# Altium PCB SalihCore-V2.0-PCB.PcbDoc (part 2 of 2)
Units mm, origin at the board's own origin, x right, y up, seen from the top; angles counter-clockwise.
Board outline 97.26 x 87.25 mm, 4 copper layers (L1(sig), L2(GND), L3(PWR), L4(sig)), stack 1.589 mm thick; 79 components, 110 nets, 368 pads, 235 vias.
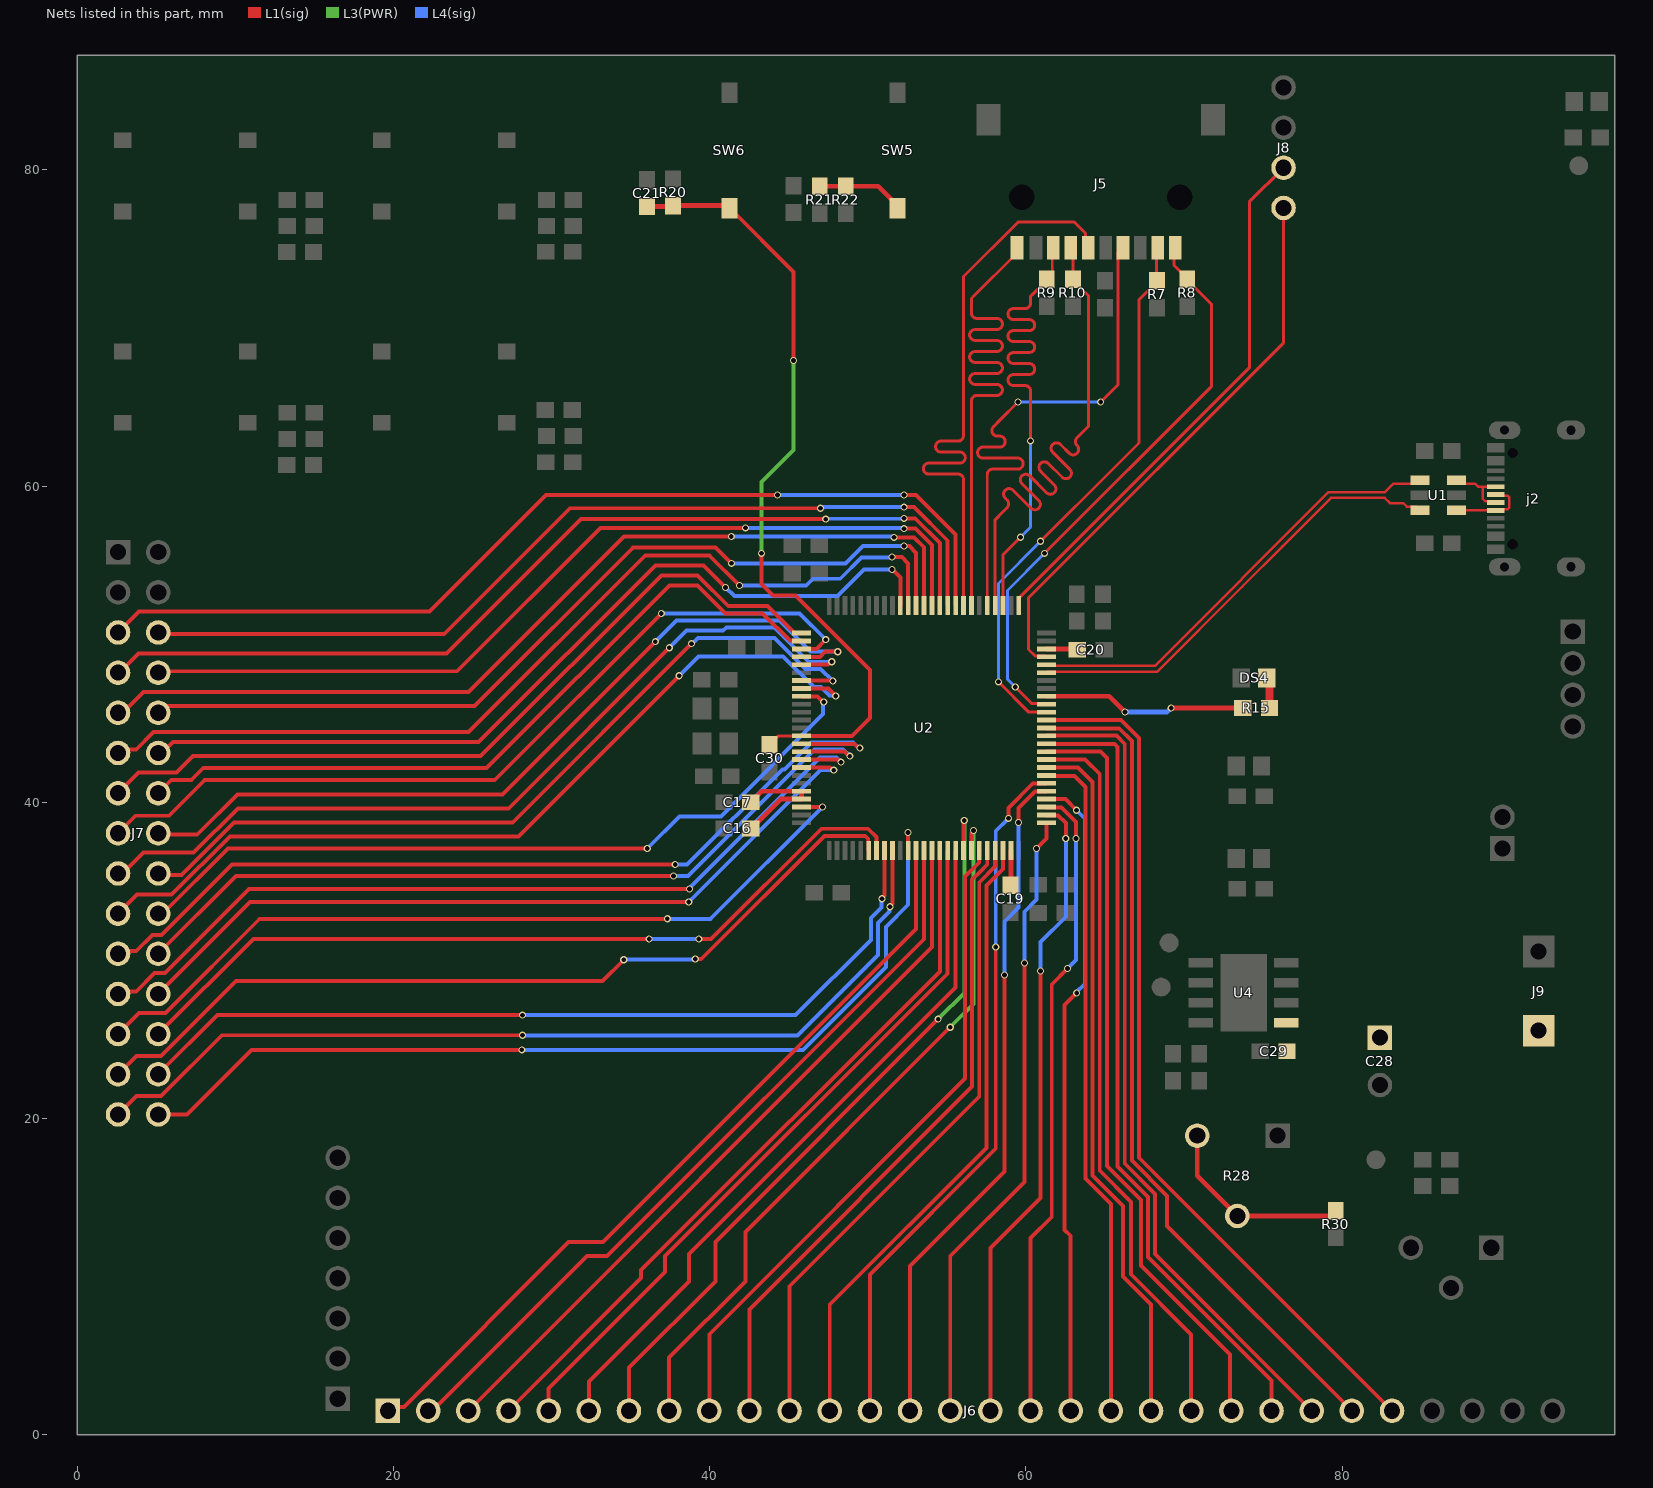
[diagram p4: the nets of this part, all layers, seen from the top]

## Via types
v1: diameter 0.45, hole 0.3, L1(sig) to L4(sig), tented both sides, 211 vias
v2: diameter 0.5, hole 0.3, L1(sig) to L4(sig), tented both sides, 24 vias

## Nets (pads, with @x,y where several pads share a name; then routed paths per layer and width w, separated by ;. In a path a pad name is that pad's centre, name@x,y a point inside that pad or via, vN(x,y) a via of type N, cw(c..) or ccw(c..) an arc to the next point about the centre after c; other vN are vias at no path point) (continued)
NetR28_1: R28.1 R28.3 R30.2 | length 12.5
  L1(sig) w0.3: R28.3@70.843,18.923 70.843,16.383 R28.1@73.383,13.843 79.264,13.843 R30.2@79.606,14.185
nRST: C21.2 C30.2 R20.2 SW6.2 U2.14 | length 50.9
  L1(sig) w0.2: C30.2@43.792,43.649 43.792,43.699 44.192,44.099 44.242,44.099 44.35,44.207 U2.14@45.813,44.207
  L1(sig) w0.25: SW6.2@41.252,77.757 41.252,77.607 45.316,73.543 v1(45.316,67.945) ; v1(43.284,55.753) 43.284,53.82 44.018,53.086 45.443,53.086 50.142,48.387 50.142,45.339 49.01,44.207 U2.14@45.813,44.207
  L1(sig) w0.3: C21.2@36.037,77.686 37.649,77.686 R20.2@37.688,77.725 37.721,77.757 SW6.2@41.252,77.757
  L3(PWR) w0.25: v1(43.284,55.753) 43.284,60.268 45.316,62.3 v1(45.316,67.945)
PA0: J7.25 U2.23 | length 51.8
  L1(sig) w0.25: J7.25@2.59,25.346 3.914,26.67 5.581,26.67 11.55,32.639 v1(37.331,32.639) ; U2.23@45.813,39.707 v1(47.138,39.707)
  L4(sig) w0.25: v1(37.331,32.639) 40.07,32.639 v1(47.138,39.707)
PA6: J7.27 U2.31 | length 54.5
  L1(sig) w0.25: J7.27@2.59,22.806 3.757,23.972 5.312,23.972 10.042,28.702 33.23,28.702 v1(34.573,30.046) ; v1(39.093,30.099) 39.474,30.099 47.257,37.882 49.848,37.882 50.038,37.692 50.038,36.982 U2.31@50.063,36.957
  L4(sig) w0.25: v1(34.573,30.046) 34.6,30.072 39.067,30.072 v1(39.093,30.099)
PA7: J7.26 U2.32 | length 51.9
  L1(sig) w0.25: J7.26@5.13,25.346 11.146,31.361 v1(36.18,31.361) ; v1(39.324,31.361) 40.1,31.361 47.071,38.332 50.034,38.332 50.563,37.803 U2.32@50.563,36.957
  L4(sig) w0.25: v1(36.18,31.361) v1(39.324,31.361)
PB1: J7.30 U2.36 | length 60.1
  L1(sig) w0.25: J7.30@5.13,20.266 6.94,20.266 11.026,24.352 v1(28.127,24.352) ; v1(52.555,38.1) 52.559,38.096 52.559,36.961 U2.36@52.563,36.957
  L4(sig) w0.25: v1(28.127,24.352) 45.919,24.352 51.158,29.591 51.158,32.131 52.555,33.528 v1(52.555,38.1)
PB2: J6.1 U2.37 | length 51
  L1(sig) w0.25: J6.1@19.662,1.524 19.904,1.766 20.666,1.766 31.092,12.192 33.251,12.192 53.063,32.004 U2.37@53.063,36.957
PB3: J7.10 U2.89 | length 56.6
  L1(sig) w0.25: J7.10@5.184,45.72 5.565,46.101 25.139,46.101 35.172,56.134 40.379,56.134 v1(41.395,55.118) ; v1(52.301,56.214) 52.312,56.203 52.639,56.203 53.063,55.779 U2.89@53.063,52.457
  L4(sig) w0.25: v1(41.395,55.118) 48.603,55.118 49.698,56.214 v1(52.301,56.214)
PB4: J7.11 U2.90 | length 59.5
  L1(sig) w0.25: J7.11@2.59,43.126 2.815,43.351 3.74,43.351 4.839,44.45 24.758,44.45 35.934,55.626 39.982,55.626 v1(41.887,53.721) ; v1(51.539,55.514) 52.159,55.514 52.563,55.11 U2.90@52.563,52.457
  L4(sig) w0.25: v1(41.887,53.721) 46.115,53.721 46.538,54.144 48.265,54.144 49.62,55.499 51.524,55.499 v1(51.539,55.514)
PB5: J7.12 U2.91 | length 55.3
  L1(sig) w0.25: J7.12@5.13,43.126 5.378,43.126 6.067,43.815 7.851,43.815 25.393,43.815 36.569,54.991 39.617,54.991 v1(41.014,53.594) ; v1(51.539,54.737) 51.562,54.737 52.063,54.236 U2.91@52.063,52.457
  L4(sig) w0.25: v1(41.014,53.594) 41.564,53.044 48.084,53.044 49.777,54.737 v1(51.539,54.737)
PB10: J6.11 U2.47 | length 40.8
  L1(sig) w0.25: J6.11@45.062,1.524 45.062,9.398 57.058,21.394 57.058,34.931 58.063,35.936 U2.47@58.063,36.957
PB11: J6.12 U2.48 | length 40
  L1(sig) w0.25: J6.12@47.602,1.524 47.602,8.234 57.508,18.14 57.508,34.745 58.563,35.8 U2.48@58.563,36.957
PB12: J6.15 U2.51 | length 39.7
  L1(sig) w0.25: J6.15@55.222,1.524 55.222,11.299 59.921,15.998 v1(59.921,29.845) ; v1(60.683,37.084) 61.313,37.714 U2.51@61.313,38.707
  L4(sig) w0.25: v1(59.921,29.845) 59.921,33.084 60.683,33.846 v1(60.683,37.084)
PB13: J6.16 U2.52 | length 40.6
  L1(sig) w0.25: J6.16@57.762,1.524 57.762,11.818 60.937,14.993 v1(60.937,29.337) ; U2.52@61.313,39.207 61.338,39.182 62.048,39.182 62.531,38.699 v1(62.531,37.719)
  L4(sig) w0.25: v1(60.937,29.337) 60.937,31.174 62.531,32.768 v1(62.531,37.719)
PB14: J6.17 U2.53 | length 40.7
  L1(sig) w0.25: J6.17@60.302,1.524 60.302,12.446 61.641,13.785 61.641,28.491 v1(62.639,29.489) ; U2.53@61.313,39.707 61.338,39.682 62.253,39.682 63.181,38.754 v1(63.181,37.719)
  L4(sig) w0.25: v1(62.639,29.489) 63.181,30.031 v1(63.181,37.719)
PB15: J6.18 U2.54 | length 41.1
  L1(sig) w0.25: U2.54@61.313,40.207 62.506,40.207 v1(63.21,39.503) ; J6.18@62.842,1.524 62.842,12.573 62.461,12.954 62.461,27.185 v1(63.216,27.94)
  L4(sig) w0.25: v1(63.21,39.503) 63.731,38.982 63.731,28.509 63.216,27.994 v1(63.216,27.94)
PC0: J7.21 U2.15 | length 56.4
  L1(sig) w0.25: J7.21@2.59,30.426 2.756,30.591 3.74,30.591 4.772,31.623 5.343,31.623 9.788,36.068 v1(37.823,36.068) ; U2.15@45.813,43.707 49.18,43.707 49.453,43.434 v1(49.507,43.434)
  L4(sig) w0.25: v1(37.823,36.068) 38.586,36.068 44.601,42.084 44.743,42.084 46.458,43.799 49.088,43.799 49.453,43.434 v1(49.507,43.434)
PC1: J7.22 U2.16 | length 52.4
  L1(sig) w0.25: J7.22@5.13,30.426 10.052,35.348 10.391,35.348 v1(37.712,35.348) ; U2.16@45.813,43.207 48.537,43.207 48.818,42.926 v1(48.872,42.926)
  L4(sig) w0.25: v1(37.712,35.348) 38.643,35.348 46.644,43.349 48.447,43.349 48.87,42.926 v1(48.872,42.926)
PC2: J7.23 U2.17 | length 54.6
  L1(sig) w0.25: J7.23@2.59,27.886 2.756,28.051 3.74,28.051 4.899,29.21 5.565,29.21 10.878,34.523 v1(38.733,34.523) ; U2.17@45.813,42.707 48.094,42.707 48.256,42.545 v1(48.31,42.545)
  L4(sig) w0.25: v1(38.733,34.523) 38.733,34.572 46.994,42.832 48.023,42.832 v1(48.31,42.545)
PC3: J7.24 U2.18 | length 50.7
  L1(sig) w0.25: J7.24@5.13,27.886 10.942,33.698 v1(38.686,33.698) ; U2.18@45.813,42.207 47.632,42.207 47.802,42.037 v1(47.856,42.037)
  L4(sig) w0.25: v1(38.686,33.698) 47.025,42.037 v1(47.856,42.037)
PC4: J7.28 U2.33 | length 54.6
  L1(sig) w0.25: J7.28@5.13,22.806 8.867,26.543 10.772,26.543 v1(28.171,26.543) ; v1(50.904,33.909) 50.904,33.963 51.063,34.122 U2.33@51.063,36.957
  L4(sig) w0.25: v1(28.171,26.543) 45.443,26.543 50.2,31.3 50.2,32.697 50.862,33.359 50.862,33.629 50.866,33.633 50.866,33.871 v1(50.904,33.909)
PC5: J7.29 U2.34 | length 59.2
  L1(sig) w0.25: J7.29@2.59,20.266 3.757,21.432 5.312,21.432 9.153,25.273 v1(28.171,25.273) ; v1(51.412,33.401) 51.412,33.455 51.563,33.606 U2.34@51.563,36.957
  L4(sig) w0.25: v1(28.171,25.273) 28.186,25.258 45.556,25.258 50.65,30.353 50.65,32.385 51.374,33.109 51.374,33.363 v1(51.412,33.401)
PC6: J6.25 U2.63 | length 53.9
  L1(sig) w0.25: U2.63@61.313,44.707 61.338,44.682 65.911,44.682 66.71,43.883 66.71,17.34 68.938,15.112 68.938,13.208 J6.25@80.622,1.524
PC7: J6.26 U2.64 | length 55.3
  L1(sig) w0.25: U2.64@61.47,45.207 66.022,45.207 67.16,44.069 67.16,17.526 J6.26@83.162,1.524
PC13: J7.18 U2.7 | length 52.1
  L1(sig) w0.25: J7.18@5.13,35.506 5.218,35.418 6.598,35.418 9.915,38.735 27.552,38.735 v1(38.855,50.038) ; U2.7@45.813,47.707 47.684,47.707 47.756,47.635 v1(47.798,47.677)
  L4(sig) w0.25: v1(38.855,50.038) 38.909,50.038 39.279,50.408 44.114,50.408 46.077,48.445 47.03,48.445 v1(47.798,47.677)
PC14: J7.19 U2.8 | length 55.5
  L1(sig) w0.25: J7.19@2.59,32.966 3.787,34.163 5.98,34.163 9.663,37.846 27.917,37.846 v1(38.077,48.006) ; U2.8@45.813,47.207 47.512,47.207 v1(47.983,46.736)
  L4(sig) w0.25: v1(38.077,48.006) 39.305,49.234 44.652,49.234 46.594,47.292 47.062,47.292 47.58,46.774 47.945,46.774 v1(47.983,46.736)
PC15: J7.20 U2.9 | length 49.6
  L1(sig) w0.25: J7.20@5.13,32.966 5.419,32.966 9.537,37.084 v1(36.061,37.084) ; U2.9@45.813,46.707 46.815,46.707 47.167,46.355 v1(47.221,46.355)
  L4(sig) w0.25: v1(36.061,37.084) 38.093,39.116 40.722,39.116 47.183,45.577 47.183,46.317 v1(47.221,46.355)
PD3: J7.5 U2.84 | length 62.1
  L1(sig) w0.25: J7.5@2.59,50.746 3.914,52.07 22.284,52.07 29.65,59.436 v1(44.3,59.436) ; v1(52.301,59.436) 53.063,59.436 55.563,56.936 U2.84@55.563,52.457
  L4(sig) w0.25: v1(44.3,59.436) v1(52.301,59.436)
PD4: J7.6 U2.85 | length 58.2
  L1(sig) w0.25: J7.6@5.13,50.658 23.22,50.658 31.164,58.603 v1(47.023,58.603) ; v1(52.301,58.674) 52.936,58.674 55.063,56.547 U2.85@55.063,52.457
  L4(sig) w0.25: v1(47.023,58.603) 47.061,58.641 47.203,58.641 47.236,58.674 v1(52.301,58.674)
PD5: J7.7 U2.86 | length 60.6
  L1(sig) w0.25: J7.7@2.59,48.118 3.875,49.403 23.361,49.403 31.87,57.912 v1(47.348,57.912) ; v1(52.301,57.964) 53.01,57.964 54.563,56.411 U2.86@54.563,52.457
  L4(sig) w0.25: v1(47.348,57.912) 47.374,57.938 52.276,57.938 v1(52.301,57.964)
PD6: J7.8 U2.87 | length 57
  L1(sig) w0.25: J7.8@5.13,48.293 24.029,48.293 33.098,57.362 v1(42.268,57.362) ; v1(52.301,57.314) 52.304,57.311 53.026,57.311 54.063,56.274 U2.87@54.063,52.457
  L4(sig) w0.25: v1(42.268,57.362) 52.112,57.362 52.122,57.352 52.263,57.352 v1(52.301,57.314)
PD7: J7.9 U2.88 | length 59.6
  L1(sig) w0.25: J7.9@2.59,45.666 2.87,45.666 4.194,46.99 24.758,46.99 34.58,56.812 v1(41.379,56.812) ; v1(51.666,56.764) 52.937,56.764 53.563,56.138 U2.88@53.563,52.457
  L4(sig) w0.25: v1(41.379,56.812) 41.471,56.812 41.472,56.811 51.565,56.811 51.612,56.764 v1(51.666,56.764)
PD8: J6.14 U2.55 | length 43.2
  L1(sig) w0.25: J6.14@52.682,1.524 52.682,10.674 58.651,16.643 v1(58.651,29.083) ; v1(59.54,38.735) 59.54,39.644 60.579,40.682 61.288,40.682 U2.55@61.313,40.707
  L4(sig) w0.25: v1(58.651,29.083) 58.651,32.45 59.54,33.339 v1(59.54,38.735)
PD9: J6.13 U2.56 | length 44.8
  L1(sig) w0.25: J6.13@50.142,1.524 50.142,10.138 58.101,18.097 v1(58.101,30.861) ; v1(58.905,38.989) 58.905,39.645 60.442,41.182 61.288,41.182 U2.56@61.313,41.207
  L4(sig) w0.25: v1(58.101,30.861) 58.101,38.185 v1(58.905,38.989)
PD10: J6.19 U2.57 | length 42.9
  L1(sig) w0.25: U2.57@61.313,41.707 61.338,41.682 63.07,41.682 63.766,40.986 63.766,16.22 65.382,14.604 J6.19@65.382,1.524
PD11: J6.20 U2.58 | length 44.6
  L1(sig) w0.25: U2.58@61.313,42.207 63.307,42.207 64.216,41.298 64.216,16.406 66.144,14.478 66.144,10.028 67.922,8.25 J6.20@67.922,1.524
PD12: J6.21 U2.59 | length 46.4
  L1(sig) w0.25: U2.59@61.313,42.707 63.754,42.707 64.678,41.783 64.678,16.706 66.652,14.732 66.652,10.157 70.462,6.347 J6.21@70.462,1.524
PD13: J6.22 U2.60 | length 48.5
  L1(sig) w0.25: U2.60@61.313,43.207 64.72,43.207 65.128,42.799 65.128,17.012 67.276,14.864 67.276,10.714 72.91,5.08 72.91,1.616 J6.22@73.002,1.524
PD14: J6.23 U2.61 | length 50.6
  L1(sig) w0.25: U2.61@61.313,43.707 65.613,43.707 65.81,43.51 65.81,16.967 67.726,15.051 67.726,11.244 75.542,3.428 J6.23@75.542,1.524
PD15: J6.24 U2.62 | length 52.2
  L1(sig) w0.25: U2.62@61.313,44.207 61.338,44.232 65.725,44.232 66.26,43.696 66.26,17.153 68.176,15.237 68.176,11.43 J6.24@78.082,1.524
PE2: J7.13 U2.1 | length 50.4
  L1(sig) w0.25: J7.13@2.59,40.586 3.885,41.88 6.298,41.88 7.343,42.926 25.52,42.926 36.95,54.356 39.236,54.356 41.183,52.409 43.661,52.409 45.363,50.707 U2.1@45.813,50.707
PE3: J7.14 U2.2 | length 47.6
  L1(sig) w0.25: J7.14@5.13,40.586 5.975,41.43 7.245,41.43 7.978,42.164 25.901,42.164 37.458,53.721 39.235,53.721 40.997,51.959 43.352,51.959 45.079,50.232 45.788,50.232 U2.2@45.813,50.207
PE4: J7.15 U2.3 | length 53
  L1(sig) w0.25: J7.15@2.59,38.046 3.7,39.155 5.808,39.155 8.055,41.402 26.409,41.402 v1(36.95,51.943) ; U2.3@45.813,49.707 46.763,49.707 v1(47.348,50.292)
  L4(sig) w0.25: v1(36.95,51.943) 36.966,51.959 45.681,51.959 v1(47.348,50.292)
PE5: J7.16 U2.4 | length 51.9
  L1(sig) w0.25: J7.16@5.13,38.046 5.218,37.958 7.599,37.958 10.153,40.513 26.917,40.513 v1(36.569,50.165) ; U2.4@45.813,49.207 46.994,49.207 47.317,49.53 v1(48.11,49.53)
  L4(sig) w0.25: v1(36.569,50.165) 37.913,51.509 44.411,51.509 46.39,49.53 v1(48.11,49.53)
PE6: J7.17 U2.5 | length 54.5
  L1(sig) w0.25: J7.17@2.59,35.506 2.87,35.506 4.194,36.83 7.374,36.83 10.168,39.624 27.298,39.624 v1(37.458,49.784) ; U2.5@45.813,48.707 47.487,48.707 47.675,48.895 v1(47.729,48.895)
  L4(sig) w0.25: v1(37.458,49.784) 38.532,50.858 40.857,50.858 41.058,51.059 44.099,51.059 46.263,48.895 v1(47.729,48.895)
PE7: J6.2 U2.38 | length 49.3
  L1(sig) w0.25: J6.2@22.202,1.524 22.449,1.524 22.741,1.815 22.764,1.815 32.251,11.303 33.521,11.303 53.563,31.345 U2.38@53.563,36.957
PE8: J6.3 U2.39 | length 47.6
  L1(sig) w0.25: J6.3@24.742,1.524 54.063,30.845 U2.39@54.063,36.957
PE9: J6.4 U2.40 | length 46.7
  L1(sig) w0.25: J6.4@27.282,1.524 35.664,9.906 35.664,10.414 54.563,29.313 U2.40@54.563,36.957
PE10: J6.5 U2.41 | length 45.9
  L1(sig) w0.25: J6.5@29.822,1.524 29.822,2.921 37.188,10.287 37.188,11.302 55.063,29.177 U2.41@55.063,36.957
PE11: J6.6 U2.42 | length 45
  L1(sig) w0.25: J6.6@32.362,1.524 32.362,3.362 38.712,9.712 38.712,11.43 55.563,28.281 U2.42@55.563,36.957
PE12: J6.7 U2.43 | length 48
  L1(sig) w0.25: J6.7@34.902,1.524 34.902,4.251 40.363,9.712 40.363,12.192 v1(54.46,26.289) ; U2.43@56.063,36.957 56.063,38.673 56.073,38.682 56.073,38.824 v1(56.111,38.862)
  L3(PWR) w0.25: v1(54.46,26.289) 56.111,27.94 v1(56.111,38.862)
PE13: J6.8 U2.44 | length 46
  L1(sig) w0.25: J6.8@37.442,1.524 37.442,4.886 42.268,9.712 42.268,12.827 v1(55.222,25.781) ; U2.44@56.563,36.957 56.563,38.046 56.69,38.173 v1(56.69,38.227)
  L3(PWR) w0.25: v1(55.222,25.781) 56.69,27.248 v1(56.69,38.227)
PE14: J6.9 U2.45 | length 42.5
  L1(sig) w0.25: J6.9@39.982,1.524 39.982,6.35 56.158,22.526 56.158,35.304 57.038,36.184 57.038,36.932 U2.45@57.063,36.957
PE15: J6.10 U2.46 | length 41.7
  L1(sig) w0.25: J6.10@42.522,1.524 42.522,7.933 56.608,22.019 56.608,35.117 57.127,35.636 57.563,36.072 U2.46@57.563,36.957
RED: DS4.A R15.2 | length 2
  L1(sig) w0.5: DS4.A@75.237,47.879 75.414,47.702 R15.2@75.414,45.974
RED_LED: R15.1 U2.67 | length 12.9
  L1(sig) w0.3: U2.67@61.313,46.707 65.284,46.707 v1(66.271,45.72) ; v1(69.192,45.974) R15.1@73.714,45.974
  L4(sig) w0.3: v1(66.271,45.72) 68.938,45.72 v1(69.192,45.974)
SDIO_CD: J5.9 U2.82 | length 37.7
  L1(sig) w0.187: U2.82@56.563,52.457 56.563,64.6 56.563,65.389 cw(c56.911,65.389) 56.911,65.737 58.174,65.737 ccw(c58.174,66.085) 58.521,66.085 ccw(c58.174,66.085) 58.174,66.432 56.798,66.432 cw(c56.798,66.78) 56.451,66.78 cw(c56.798,66.78) 56.798,67.128 58.176,67.128 ccw(c58.176,67.475) 58.523,67.475 ccw(c58.176,67.475) 58.176,67.823 56.798,67.823 cw(c56.798,68.171) 56.451,68.171 cw(c56.798,68.171) 56.798,68.518 58.177,68.518 ccw(c58.177,68.866) 58.525,68.866 ccw(c58.177,68.866) 58.177,69.214 56.798,69.214 cw(c56.798,69.561) 56.451,69.561 cw(c56.798,69.561) 56.798,69.909 58.179,69.909 ccw(c58.179,70.257) 58.527,70.257 ccw(c58.179,70.257) 58.179,70.604 56.911,70.604 cw(c56.911,70.952) 56.563,70.952 56.563,71.872 56.7,72.009 59.373,74.682 J5.9@59.373,75.032
SDIO_CK: J5.5 U2.80 | length 35.6
  L1(sig) w0.187: U2.80@57.563,52.457 57.563,59.944 57.563,60.733 cw(c57.911,60.733) 57.911,61.081 59.486,61.081 ccw(c59.486,61.428) 59.834,61.428 ccw(c59.486,61.428) 59.486,61.776 57.298,61.776 cw(c57.298,62.124) 56.951,62.124 cw(c57.298,62.124) 57.298,62.471 58.351,62.471 ccw(c58.351,62.819) 58.699,62.819 ccw(c58.351,62.819) 58.351,63.167 58.196,63.167 cw(c58.196,63.514) 57.951,63.76 58.325,64.135 v1(59.506,65.315) ; v1(64.737,65.329) 65.841,66.433 65.841,74.8 J5.5@66.073,75.032
  L4(sig) w0.187: v1(59.506,65.315) 59.513,65.322 64.73,65.322 v1(64.737,65.329)
SDIO_CMD: J5.3 U2.83 | length 38.9
  L1(sig) w0.187: U2.83@56.063,52.457 56.063,60.325 56.063,60.419 ccw(c55.716,60.419) 55.716,60.766 53.871,60.766 cw(c53.871,61.114) 53.523,61.114 cw(c53.871,61.114) 53.871,61.462 55.828,61.462 ccw(c55.828,61.809) 56.176,61.809 ccw(c55.828,61.809) 55.828,62.157 54.64,62.157 cw(c54.64,62.505) 54.292,62.505 cw(c54.64,62.505) 54.64,62.852 55.716,62.852 ccw(c55.716,63.2) 56.063,63.2 56.063,64.389 56.063,73.252 59.519,76.708 63.06,76.708 63.776,75.992 63.776,75.242 J5.3@63.947,75.071
SDIO_D1: J5.8 R8.1 U2.66 | length 36.7
  L1(sig) w0.187: v1(59.336,47.293) 60.366,46.263 61.257,46.263 U2.66@61.313,46.207 ; v1(61.191,55.753) 71.732,66.294 71.732,71.516 70.216,73.032 R8.1@70.216,73.082 70.216,73.132 69.373,73.975 J5.8@69.373,75.032
  L4(sig) w0.187: v1(59.336,47.293) 58.846,47.783 58.846,53.407 v1(61.191,55.753)
SDIO_D2: J5.1 R9.1 U2.78 | length 34.5
  L1(sig) w0.187: U2.78@58.563,52.457 58.563,55.665 v1(59.667,56.769) ; v1(60.302,62.865) 60.302,65.924 60.302,66.018 ccw(c59.955,66.018) 59.955,66.365 59.223,66.365 cw(c59.223,66.713) 58.875,66.713 cw(c59.223,66.713) 59.223,67.061 60.217,67.061 ccw(c60.217,67.408) 60.565,67.408 ccw(c60.217,67.408) 60.217,67.756 59.223,67.756 cw(c59.223,68.104) 58.875,68.104 cw(c59.223,68.104) 59.223,68.451 60.217,68.451 ccw(c60.217,68.799) 60.565,68.799 ccw(c60.217,68.799) 60.217,69.147 59.223,69.147 cw(c59.223,69.494) 58.875,69.494 cw(c59.223,69.494) 59.223,69.842 60.217,69.842 ccw(c60.217,70.19) 60.565,70.19 ccw(c60.217,70.19) 60.217,70.537 59.223,70.537 cw(c59.223,70.885) 58.875,70.885 cw(c59.223,70.885) 59.223,71.233 59.955,71.233 ccw(c59.955,71.58) 60.302,71.58 60.302,72.004 60.371,72.072 61.326,73.028 R9.1@61.326,73.078 61.673,73.425 J5.1@61.673,75.032
  L4(sig) w0.187: v1(59.667,56.769) 60.302,57.404 v1(60.302,62.865)
SDIO_D3: J5.2 R10.1 U2.79 | length 38.6
  L1(sig) w0.187: U2.79@58.063,52.457 58.063,57.883 58.562,58.382 58.753,58.573 58.819,58.639 ccw(c58.573,58.885) 58.819,59.131 58.7,59.25 cw(c58.946,59.496) 58.7,59.741 cw(c58.946,59.496) 59.191,59.741 60.327,58.606 ccw(c60.573,58.851) 60.819,58.606 ccw(c60.573,58.851) 60.819,59.097 59.753,60.164 cw(c59.998,60.41) 59.753,60.655 cw(c59.998,60.41) 60.244,60.655 61.31,59.589 ccw(c61.556,59.835) 61.802,59.589 ccw(c61.556,59.835) 61.802,60.081 60.936,60.947 cw(c61.182,61.193) 60.936,61.439 cw(c61.182,61.193) 61.428,61.439 62.293,60.573 ccw(c62.539,60.819) 62.785,60.573 ccw(c62.539,60.819) 62.785,61.064 61.699,62.15 cw(c61.945,62.396) 61.699,62.642 cw(c61.945,62.396) 62.191,62.642 62.751,62.082 ccw(c62.997,62.328) 63.243,62.082 ccw(c62.997,62.328) 63.243,62.574 cw(c63.488,62.819) 63.243,63.065 63.962,63.785 63.962,64.901 63.962,72.044 62.977,73.028 R10.1@62.977,73.078 62.977,74.828 J5.2@62.773,75.032
SDIO_DO: J5.7 R7.1 U2.65 | length 35.4
  L1(sig) w0.187: v1(58.27,47.625) 60.188,45.707 U2.65@61.313,45.707 ; v1(60.937,56.515) 65.509,61.087 67.16,62.738 67.16,66.802 67.16,71.793 68.273,72.906 J5.7@68.273,75.032
  L4(sig) w0.187: v1(58.27,47.625) 58.27,53.848 v1(60.937,56.515)
SW1: R21.2 R22.2 SW5.1 | length 5.6
  L1(sig) w0.3: R21.2@46.967,78.966 R22.2@48.618,78.966 50.654,78.966 51.888,77.732 SW5.1@51.888,77.582
SYS_SWCL: J8.2 U2.76 | length 34.6
  L1(sig) w0.2: U2.76@59.563,52.457 59.563,52.907 74.145,67.489 74.145,77.978 J8.2@76.304,80.137
SYS_SWDIO: J8.1 U2.72 | length 35.9
  L1(sig) w0.2: U2.72@61.313,49.207 61.263,49.257 60.589,49.257 60.175,49.671 60.175,52.953 76.304,69.082 J8.1@76.304,77.597
USB_N: j2.5 j2.7 U1.1 | length 5
  L1(sig) w0.158: U1.1@87.233,58.486 87.251,58.468 j2.5@89.732,58.468 89.803,58.538 90.474,58.538 90.567,58.631 90.567,59.305 90.474,59.397 89.803,59.397 j2.7@89.732,59.468
USB_OTG_FS_N: U1.6 U2.70 | length 28.5
  L1(sig) w0.158: U2.70@61.313,48.207 61.383,48.276 68.32,48.276 73.681,53.638 76.233,56.189 79.303,59.259 82.704,59.259 83.035,58.928 83.875,58.928 84.096,58.707 84.712,58.707 U1.6@84.933,58.486
USB_OTG_FS_P: U1.4 U2.71 | length 28.5
  L1(sig) w0.158: U2.71@61.313,48.707 61.383,48.638 68.17,48.638 79.153,59.621 82.712,59.621 83.256,60.165 84.712,60.165 U1.4@84.933,60.386
USB_P: j2.6 j2.8 U1.3 | length 4.4
  L1(sig) w0.158: U1.3@87.233,60.386 87.454,60.165 88.409,60.165 88.606,59.968 j2.8@89.732,59.968 ; 89.028,59.968 88.903,59.843 88.903,59.202 89.067,59.039 89.661,59.039 j2.6@89.732,58.968
VCAP1: C19.2 U2.49 | length 2.2
  L1(sig) w0.3: C19.2@59.032,34.759 59.063,34.79 U2.49@59.063,36.957
VCAP2: C20.2 U2.73 | length 2
  L1(sig) w0.3: U2.73@61.313,49.707 63.212,49.707 C20.2@63.262,49.657
VDDA: C16.2 C17.2 U2.21 U2.22 | length 8
  L1(sig) w0.3: C16.2@42.61,38.354 42.66,38.354 44.513,40.207 U2.22@45.813,40.207 U2.21@45.813,40.707 43.312,40.707 43.01,40.405 43.01,40.355 42.66,40.005 C17.2@42.61,40.005
VM: C28.1 C29.2 J9.2 U4.5
pads on no net: j2. j2.3 j2.9 J5. J5.10 SW1.2 SW1.4 SW2.2 SW2.4 SW3.2 SW3.4 SW4.2 SW4.4
copper on no net: | length 28.9
  L1(sig) w0.3: v1(89.004,73.012) 89.004,74.194 ; 90.362,66.027 90.362,68.248 90.377,68.263 90.377,70.599 90.594,70.816 90.594,73.938 ; 91.544,73.938 91.544,71.957 91.906,71.595 91.956,71.595 92.306,71.245 92.306,71.195 ; v1(92.306,68.44) 92.306,69.647 ; 92.494,73.938 94.209,73.938 94.338,74.067 95.221,74.067 96.229,75.076 96.229,76.249 ; 92.494,75.866 92.494,75.854 92.624,75.724 v1(93.207,75.724)
  L1(sig) w0.5: v1(78.701,68.326) 80.122,68.326 ; 81.722,68.326 81.811,68.238 81.811,66.51 81.899,66.421 ; 82.019,84.906 v1(82.019,86.106) ; v1(85.321,72.885) 86.801,72.885 86.845,72.929 ; v1(85.956,70.599) 87.327,70.599 ; v1(96.243,71.361) 96.243,73.063

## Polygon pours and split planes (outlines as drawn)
GND on L1(sig) "GND_L01_P025" (solid, pour order 25): 93.472,74.501 90.17,74.501 90.17,75.253 92.075,75.253 92.075,76.708 93.472,76.708
+3V3 on L1(sig) "+3V3_L01_P019" (solid, pour order 19): 74.465,81.28 74.526,84.074 83.67,84.074 83.664,86.224 88.14,86.224 88.14,77.47 84.647,77.47 84.647,69.342 88.14,69.342 88.14,66.802 89.639,66.802 89.639,65.278 79.225,65.278 79.101,81.28
no net on L1(sig) "NONET_L01_P006" (solid, pour order 6): 94.973,75.248 93.703,75.248 93.703,77.579 91.544,77.579 91.544,79.566 93.576,79.566 94.973,78.169
no net on L1(sig) "NONET_L01_P005" (solid, pour order 5): 92.052,75.311 91.036,75.311 91.036,76.581 89.258,78.105 89.258,86.36 92.052,86.36
+5V on L1(sig) "+5V_L01_P004" (solid, pour order 4): 90.821,76.683 90.821,75.302 86.172,75.32 86.172,74.865 85.063,74.871 85.049,74.858 85.042,74.864 85.042,76.714
MOTOR_OUT1 on L1(sig) "MOTOR_OUT1_L01_P010" (solid, pour order 10): 75.605,26.957 75.61,26.961 75.61,27.716 77.515,27.716 89.566,38.1 93.009,38.1 93.009,36.479 93.009,36.098 77.355,26.827 75.61,26.827 75.61,26.954
MOTOR_OUT2 on L1(sig) "MOTOR_OUT2_L01_P009" (solid, pour order 9): 75.61,30.256 86.121,40.767 93.136,40.767 93.136,37.338 85.486,37.338 77.515,29.367 75.61,29.367
VM on L1(sig) "VM_L01_P008" (solid, pour order 8): 75.61,26.446 75.61,23.398 94.608,23.398 94.608,27.813 87.623,27.813 87.623,27.051 77.993,27.051 77.388,26.446
GND on L1(sig) "GND_L01_P023" (solid, pour order 23): 90.391,53.92 90.393,53.92 90.393,56.4 89.191,56.4 89.191,56.188 88.242,56.172 88.242,53.92
GND on L1(sig) "GND_L01_P022" (solid, pour order 22): 90.391,64.516 90.393,64.516 90.393,62.036 89.191,62.036 89.191,62.249 88.242,62.264 88.242,64.516
+5V on L1(sig) "+5V_L01_P012" (solid, pour order 12): 88.369,57.277 88.369,56.261 88.877,56.261 88.935,56.515 90.274,56.515 90.528,56.769 91.798,56.769 91.798,57.785 90.528,57.785 90.528,57.277
+5V on L1(sig) "+5V_L01_P011" (solid, pour order 11): 88.369,61.214 88.369,62.23 88.877,62.23 88.935,61.976 90.274,61.976 90.528,61.722 91.544,61.722 91.544,60.804 90.528,60.804 90.528,61.214
GND on L1(sig) "GND_L01_P020" (solid, pour order 20): 46.586,46.454 46.586,45.895 42.444,45.895 41.633,45.085 40.49,45.085 40.49,48.768 43.157,48.768 44.046,47.879 44.046,46.454
GND on L1(sig) "GND_L01_P021" (solid, pour order 21): 40.173,44.45 40.173,41.021 37.315,41.021 37.315,44.45
GND on L1(sig) "GND_L01_P007" (solid, pour order 7): 72.054,23.652 72.054,29.367 70.149,29.367 70.149,30.383 72.054,30.383 72.054,31.653 75.483,31.653 75.483,29.005 77.388,29.005 77.388,28.224 75.356,28.224 75.356,23.652
+3V3 on L3(PWR) "+3V3_L03_P016" (solid, remove dead copper, pour order 16): 92.941,0 92.941,87.249 0,87.249 0,0
+5V on L3(PWR) "+5V_L03_P015" (solid, pour order 15): 97.259,0 83.256,0 83.256,3.81 86.264,3.81 86.268,4.496 86.591,58.547 83.256,58.547 83.256,62.23 89.893,62.23 89.893,71.841 84.686,71.841 84.686,77.737 92.56,77.737 92.665,87.249 97.259,87.249
GND on L2(GND) "GND_L02_P013" (solid, pour order 13): 0,0 0,87.249 97.259,87.249 97.259,0

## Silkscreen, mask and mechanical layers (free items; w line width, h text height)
Top Overlay:
  lines w0.3: 85.194,26.035 87.48,26.035 ; 86.337,24.638 86.337,27.178 ; 86.337,29.337 86.337,31.877
  text "BUTTON-1" at 30.959,79.234 h1.5 r90
  text "BUTTON-4" at 14.576,79.107 h1.5 r90
  text "RESET" at 38.642,73.473 h1.5
  text "BOOT-0" at 49.564,73.473 h1.5
  text "BUTTON-2" at 30.959,66.026 h1.5 r90
  text "BUTTON-3" at 14.576,65.772 h1.5 r90
  text "+3V3" at 83.217,65.513 h0.7
  text "+3V3  GND" at 7.485,55.255 h1.2
  text "+3V3  GND" at 7.485,52.697 h1.2
  text "PD3  PD4" at 7.485,50.139 h1.2
  text "PD5  PD6" at 7.485,47.581 h1.2
  text "RED" at 71.83,46.849 h0.7 r90
  text "PD7  PB3" at 7.485,45.023 h1.2
  text "I2C-LCD" at 91.002,44.542 h1.5 r90
  text "PB4  PB5" at 7.485,42.464 h1.2
  text "GREEN" at 71.957,40.993 h0.7 r90
  text "PE2  PE3" at 7.485,39.906 h1.2
  text "PE4  PE5" at 7.485,37.348 h1.2
  text "BLUE" at 71.898,35.407 h0.7 r90
  text "PE6  PC13" at 7.485,34.79 h1.2
  text "MOTOR-OUT" at 87.527,34.541 h1.5 r90
  text "PC14  PC15" at 7.485,32.232 h1.2
  text "IN2" at 68.378,31.994 h0.7
  text "PC0  PC1" at 7.485,29.674 h1.2
  text "PC2  PC3" at 7.485,27.116 h1.2
  text "IN1" at 67.87,26.66 h0.7
  text "PA0  PA7" at 7.485,24.557 h1.2
  text "FIXED" at 71.959,22.325 h0.7
  text "PA6  PC4" at 7.485,21.999 h1.2
  text "ADJ" at 68.203,21.817 h0.7 r90
  text "MOTOR-VM" at 88.239,20.273 h1.5
  text "PC5  PB1" at 7.485,19.441 h1.2
  text "MOTOR-CNT" at 80.136,18.269 h0.7
  text "GND" at 7.308,15.925 h1.2
  text "+3V3" at 7.308,13.363 h1.2
  text "LORA-AUX" at 7.308,10.802 h1.2
  text "ILIM Control" at 69.381,9.375 h1.5
  text "LORA-TXD" at 7.308,8.241 h1.2
  text "Motor Control" at 92.783,7.968 h1.5 r90
  text "LORA-RXD" at 7.308,5.68 h1.2
  text "LORA MODULE" at 5.348,4.311 h1.5 r90
  text "PB2" at 20.209,3.284 h1.2 r90
  text "PE7" at 22.745,3.284 h1.2 r90
  text "PE8" at 25.28,3.284 h1.2 r90
  text "PE9" at 27.816,3.284 h1.2 r90
  text "PE10" at 30.352,3.284 h1.2 r90
  text "PE11" at 32.887,3.284 h1.2 r90
  text "PE12" at 35.423,3.284 h1.2 r90
  text "PE13" at 37.958,3.284 h1.2 r90
  text "PE14" at 40.494,3.284 h1.2 r90
  text "PE15" at 43.03,3.284 h1.2 r90
  text "PE16" at 45.565,3.284 h1.2 r90
  text "PB11" at 48.101,3.284 h1.2 r90
  text "PD9" at 50.636,3.284 h1.2 r90
  text "PD8" at 53.172,3.284 h1.2 r90
  text "PB12" at 55.708,3.284 h1.2 r90
  text "PB13" at 58.243,3.284 h1.2 r90
  text "PB14" at 60.779,3.284 h1.2 r90
  text "PB15" at 63.315,3.284 h1.2 r90
  text "PD10" at 65.85,3.284 h1.2 r90
  text "PD11" at 68.386,3.284 h1.2 r90
  text "PD12" at 70.921,3.284 h1.2 r90
  text "PD13" at 73.457,3.284 h1.2 r90
  text "PD14" at 75.993,3.284 h1.2 r90
  text "PD15" at 78.528,3.284 h1.2 r90
  text "PC6" at 81.064,3.284 h1.2 r90
  text "PC7" at 83.6,3.284 h1.2 r90
  text "+5V" at 86.135,3.284 h1.2 r90
  text "GND" at 88.671,3.284 h1.2 r90
  text "+5V" at 91.206,3.284 h1.2 r90
  text "+GND" at 93.742,3.284 h1.2 r90
  text "LORA-M1" at 7.308,3.119 h1.2
  text "LORA-M0" at 7.308,0.558 h1.2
